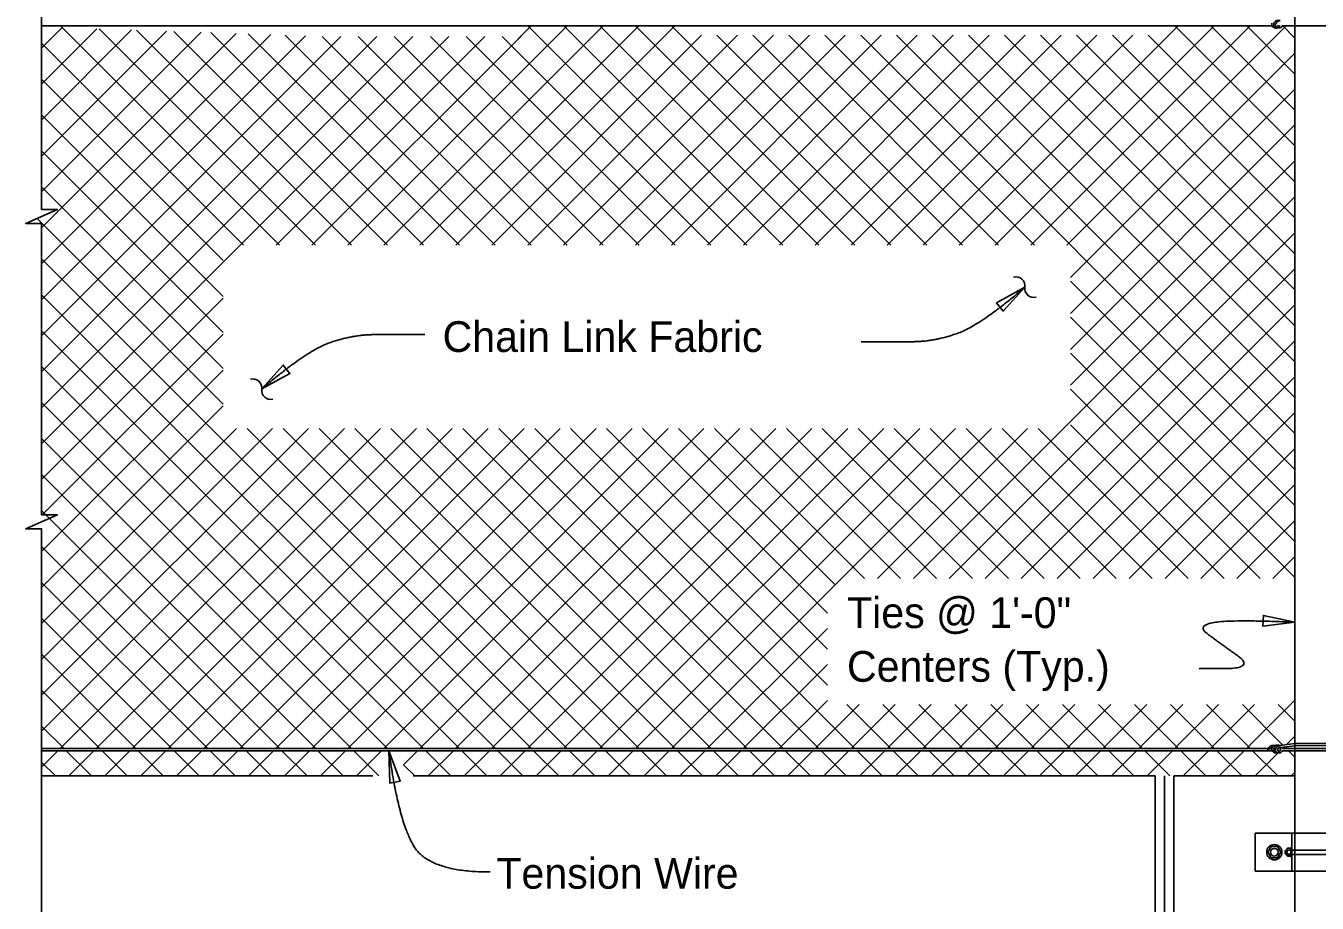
# Model space of a CAD drawing. Extents: x 0 to 41, y -96 to 25.
# Drawn here: x 16.86 to 25.32, y 14.8 to 20.56 of the extents above; entities that cross this region are included whole.
import ezdxf

# ---------------------------------------------------------------- set-up
doc = ezdxf.new("R2010")
doc.units = 0
for name, color, linetype in [('CL_Major', 7, 'Continuous'), ('Dimension', 7, 'Continuous'), ('Miscellaneous', 7, 'Continuous'), ('SteelMisc', 7, 'Continuous'), ('SteelMisc_h', 7, 'Continuous'), ('SupstrConc', 7, 'Continuous'), ('TextStructures', 7, 'Continuous')]:
    doc.layers.add(name, color=color, linetype=linetype)

msp = doc.modelspace()

# ---------------------------------------------------------------- linework, layer by layer
at = {"layer": 'CL_Major'}
msp.add_line((24.3238, 9.7541), (24.3238, 15.6384), dxfattribs=at)
at = {"layer": 'Dimension'}
for points in [[(16.9607, 22.5181), (16.9607, 19.3509), (17.064, 19.3509), (16.9607, 19.3059), (16.8574, 19.2609), (16.9607, 19.2609), (16.9607, 18.3673)], [(16.9607, 18.3673), (16.9607, 17.3495), (17.064, 17.3495), (16.9607, 17.3045), (16.8574, 17.2595), (16.9607, 17.2595), (16.9607, 15.0552)], [(16.9607, 15.3052), (16.9607, 13.4544), (17.064, 13.4544), (16.9607, 13.4094), (16.8574, 13.3644), (16.9607, 13.3644), (16.9607, 11.3636)]]:
    msp.add_lwpolyline(points, dxfattribs=at)
for points in [[(23.4077, 18.8419), (23.2222, 18.7409), (23.2658, 18.6855)], [(18.4037, 18.1753), (18.5892, 18.2762), (18.5456, 18.3317)], [(25.1779, 16.6468), (24.9713, 16.6906), (24.9684, 16.6201)], [(19.2384, 15.8029), (19.2433, 15.5918), (19.3126, 15.6052)]]:
    msp.add_lwpolyline(points, close=True, dxfattribs=at)
for centre, start, end in [((23.3481, 18.8503), 352.34263, 104.06985), ((23.4663, 18.8345), 172.34263, 284.06985), ((18.3451, 18.1827), 352.34263, 104.06985), ((18.4633, 18.1668), 172.34263, 284.06985)]:
    msp.add_arc(centre, 0.0596, start, end, dxfattribs=at)
for points in [[(22.3345, 18.4855), (22.5366, 18.4855), (22.8102, 18.4855), (23.117, 18.5934), (23.4071, 18.8423)], [(19.4725, 18.5316), (19.2748, 18.5316), (19.0012, 18.5316), (18.6944, 18.4238), (18.4043, 18.1748)], [(24.5674, 16.3422), (24.502, 16.3422), (24.922, 16.3422), (24.6718, 16.5193), (24.5346, 16.622), (24.7452, 16.6645), (25.1779, 16.6467)], [(19.9014, 15.009), (19.5036, 15.009), (19.2996, 15.3459), (19.2384, 15.8029)]]:
    msp.add_open_spline(points, degree=2, dxfattribs=at)
at = {"layer": 'Miscellaneous'}
for p, q in [((16.9607, 20.4098), (17.0951, 20.5442)), ((16.9607, 20.1741), (17.3232, 20.5366)), ((16.9607, 19.9384), (17.5512, 20.5289)), ((16.9607, 19.7027), (17.7793, 20.5213)), ((16.9607, 19.467), (18.0073, 20.5136)), ((16.9607, 19.2313), (18.2354, 20.506)), ((16.9607, 18.9956), (18.4634, 20.4983)), ((16.9607, 18.7599), (18.6915, 20.4907)), ((17.0843, 20.5552), (18.5211, 19.1184)), ((17.3392, 20.536), (18.7568, 19.1184)), ((17.5826, 20.5279), (18.992, 19.1184)), ((17.8269, 20.5197), (19.2282, 19.1184)), ((18.0708, 20.5115), (19.4639, 19.1184)), ((18.3147, 20.5033), (19.6996, 19.1184)), ((18.5566, 20.4952), (19.9334, 19.1184)), ((18.5586, 20.4951), (19.9353, 19.1184)), ((18.9691, 19.1184), (20.4059, 20.5552)), ((19.2049, 19.1184), (20.6416, 20.5552)), ((19.4406, 19.1184), (20.8773, 20.5552)), ((19.6763, 19.1184), (21.113, 20.5552)), ((19.912, 19.1184), (21.2874, 20.4939)), ((20.0834, 20.4684), (20.1702, 20.5552)), ((20.1477, 19.1184), (21.5231, 20.4939)), ((20.1484, 20.5552), (21.5852, 19.1184)), ((20.3834, 19.1184), (21.7588, 20.4939)), ((20.3841, 20.5552), (21.8209, 19.1184)), ((20.6191, 19.1184), (21.9945, 20.4939)), ((20.6198, 20.5552), (22.0566, 19.1184)), ((20.8548, 19.1184), (22.2302, 20.4939)), ((20.8555, 20.5552), (22.2923, 19.1184)), ((21.0905, 19.1184), (22.4659, 20.4939)), ((21.0912, 20.5552), (21.22, 20.4265)), ((21.3262, 19.1184), (22.7017, 20.4939)), ((21.3882, 20.4939), (22.7637, 19.1184)), ((21.5619, 19.1184), (22.9374, 20.4939)), ((21.6239, 20.4939), (22.9994, 19.1184)), ((21.7976, 19.1184), (23.1731, 20.4939)), ((21.8596, 20.4939), (23.2351, 19.1184)), ((22.0333, 19.1184), (23.4088, 20.4939)), ((22.0953, 20.4939), (23.4708, 19.1184)), ((22.269, 19.1184), (23.6445, 20.4939)), ((22.331, 20.4939), (25.1779, 17.6471)), ((22.5047, 19.1184), (23.8802, 20.4939)), ((22.5667, 20.4939), (25.1779, 17.8828)), ((22.7404, 19.1184), (24.1159, 20.4939)), ((22.8024, 20.4939), (25.1779, 18.1185)), ((22.9761, 19.1184), (24.4129, 20.5552)), ((23.0382, 20.4939), (25.1779, 18.3542)), ((23.2118, 19.1184), (24.6486, 20.5552)), ((23.2739, 20.4939), (25.1779, 18.5899)), ((23.4475, 19.1184), (24.8843, 20.5552)), ((23.5096, 20.4939), (25.1779, 18.8256)), ((23.6832, 19.1184), (25.12, 20.5552)), ((23.7453, 20.4939), (25.1779, 19.0613)), ((23.981, 20.4939), (25.1779, 19.297)), ((24.2167, 20.4939), (25.1779, 19.5327)), ((24.3911, 20.5552), (25.1779, 19.7684)), ((24.6268, 20.5552), (25.1779, 20.0041)), ((24.8625, 20.5552), (25.1779, 20.2398)), ((25.0982, 20.5552), (25.1779, 20.4755)), ((16.9607, 18.2885), (19.1592, 20.487)), ((16.9607, 18.0528), (19.3949, 20.487)), ((16.9607, 18.5242), (18.9235, 20.487)), ((16.9607, 17.8166), (19.6311, 20.487)), ((16.9607, 20.4431), (18.2854, 19.1184)), ((18.4977, 19.1184), (19.8663, 20.487)), ((18.7334, 19.1184), (20.102, 20.487)), ((18.801, 20.487), (20.1696, 19.1184)), ((19.0372, 20.487), (20.4057, 19.1184)), ((19.2733, 20.487), (20.6419, 19.1184)), ((19.5095, 20.487), (20.8781, 19.1184)), ((19.7452, 20.487), (21.1138, 19.1184)), ((19.9809, 20.487), (21.3495, 19.1184)), ((21.22, 20.4265), (22.528, 19.1184)), ((23.7072, 18.9067), (25.1779, 20.3775)), ((16.9607, 20.2074), (18.1504, 19.0177)), ((23.7072, 18.671), (25.1779, 20.1418)), ((16.9607, 19.9717), (18.1504, 18.782)), ((23.7072, 18.4353), (25.1779, 19.9061)), ((16.9607, 19.736), (18.1504, 18.5463)), ((23.7072, 18.1996), (25.1779, 19.6704)), ((16.9607, 19.5003), (18.1504, 18.3106)), ((22.6764, 16.9332), (25.1779, 19.4347)), ((16.9319, 19.2934), (18.1504, 18.0749)), ((22.9121, 16.9332), (25.1779, 19.199)), ((16.9607, 19.0289), (20.1719, 15.8177)), ((23.1478, 16.9332), (25.1779, 18.9632)), ((23.7072, 18.8821), (25.1779, 17.4113)), ((16.9607, 18.7932), (19.9362, 15.8177)), ((16.9607, 17.5814), (18.1504, 18.7711)), ((23.3835, 16.9332), (25.1779, 18.7275)), ((23.7072, 18.6464), (25.1779, 17.1756)), ((16.9607, 18.5575), (19.7005, 15.8177)), ((16.9645, 17.3495), (18.1504, 18.5354)), ((23.6192, 16.9332), (25.1779, 18.4918)), ((23.7072, 18.4107), (25.1779, 16.9399)), ((16.9607, 18.3218), (19.4648, 15.8177)), ((16.9607, 17.11), (18.1504, 18.2997)), ((23.8549, 16.9332), (25.1779, 18.2561)), ((23.7072, 18.175), (24.949, 16.9332)), ((16.9607, 18.0861), (19.2291, 15.8177)), ((16.9607, 16.8743), (18.1504, 18.064)), ((24.0906, 16.9332), (25.1779, 18.0204)), ((16.9607, 15.9315), (18.9465, 17.9172)), ((16.9607, 16.4029), (18.4751, 17.9172)), ((16.9607, 16.6386), (18.2394, 17.9172)), ((16.9607, 16.1672), (18.7108, 17.9172)), ((17.0826, 15.8177), (19.1822, 17.9172)), ((17.3183, 15.8177), (19.4179, 17.9172)), ((17.554, 15.8177), (19.6536, 17.9172)), ((17.7897, 15.8177), (19.8893, 17.9172)), ((18.0254, 15.8177), (20.125, 17.9172)), ((18.2611, 15.8177), (20.3607, 17.9172)), ((18.3081, 17.9172), (20.4076, 15.8177)), ((18.4968, 15.8177), (20.5964, 17.9172)), ((18.5438, 17.9172), (20.6433, 15.8177)), ((18.7325, 15.8177), (20.8321, 17.9172)), ((18.7795, 17.9172), (20.879, 15.8177)), ((18.9682, 15.8177), (21.0678, 17.9172)), ((19.0152, 17.9172), (21.1147, 15.8177)), ((19.2039, 15.8177), (21.3035, 17.9172)), ((19.2509, 17.9172), (21.3505, 15.8177)), ((19.4396, 15.8177), (21.5392, 17.9172)), ((19.4866, 17.9172), (21.5862, 15.8177)), ((19.6753, 15.8177), (21.7749, 17.9172)), ((19.7223, 17.9172), (21.8219, 15.8177)), ((19.911, 15.8177), (22.0106, 17.9172)), ((19.958, 17.9172), (22.0576, 15.8177)), ((20.1467, 15.8177), (22.2463, 17.9172)), ((20.1937, 17.9172), (22.2933, 15.8177)), ((20.3824, 15.8177), (22.482, 17.9172)), ((20.4294, 17.9172), (22.1126, 16.234)), ((20.6181, 15.8177), (22.7177, 17.9172)), ((20.6651, 17.9172), (22.1126, 16.4697)), ((20.8538, 15.8177), (22.9534, 17.9172)), ((20.9008, 17.9172), (22.1126, 16.7054)), ((21.0895, 15.8177), (23.1891, 17.9172)), ((21.1365, 17.9172), (22.1628, 16.8909)), ((21.3722, 17.9172), (22.3563, 16.9332)), ((21.6079, 17.9172), (22.592, 16.9332)), ((21.8436, 17.9172), (22.8277, 16.9332)), ((22.0793, 17.9172), (23.0634, 16.9332)), ((22.315, 17.9172), (23.2991, 16.9332)), ((22.4407, 16.9332), (23.4248, 17.9172)), ((22.5507, 17.9172), (23.5348, 16.9332)), ((22.7864, 17.9172), (23.7705, 16.9332)), ((23.0221, 17.9172), (24.0062, 16.9332)), ((23.2578, 17.9172), (24.2419, 16.9332)), ((23.4935, 17.9172), (24.4776, 16.9332)), ((23.7072, 17.9393), (24.7133, 16.9332)), ((16.9607, 17.8504), (18.9934, 15.8177)), ((24.3263, 16.9332), (25.1779, 17.7847)), ((16.9607, 17.6147), (18.7577, 15.8177)), ((24.562, 16.9332), (25.1779, 17.549)), ((16.9607, 17.379), (18.522, 15.8177)), ((24.7977, 16.9332), (25.1779, 17.3133)), ((16.9607, 17.1433), (18.2863, 15.8177)), ((25.0334, 16.9332), (25.1779, 17.0776)), ((16.9607, 16.9076), (18.0506, 15.8177)), ((16.9607, 16.6719), (17.8149, 15.8177)), ((21.3252, 15.8177), (22.1126, 16.6051)), ((16.9607, 16.4362), (17.5792, 15.8177)), ((21.5609, 15.8177), (22.1126, 16.3694)), ((16.9607, 16.2005), (17.3435, 15.8177)), ((21.7966, 15.8177), (22.1126, 16.1337)), ((22.0323, 15.8177), (22.3208, 16.1062)), ((22.2404, 16.1062), (22.529, 15.8177)), ((22.268, 15.8177), (22.5565, 16.1062)), ((22.4761, 16.1062), (22.7647, 15.8177)), ((22.5037, 15.8177), (22.7922, 16.1062)), ((22.7119, 16.1062), (23.0004, 15.8177)), ((22.7394, 15.8177), (23.028, 16.1062)), ((22.9476, 16.1062), (23.2361, 15.8177)), ((22.9751, 15.8177), (23.2637, 16.1062)), ((23.1833, 16.1062), (23.4718, 15.8177)), ((23.2108, 15.8177), (23.4994, 16.1062)), ((23.419, 16.1062), (23.7075, 15.8177)), ((23.4465, 15.8177), (23.7351, 16.1062)), ((23.6547, 16.1062), (23.9432, 15.8177)), ((23.6822, 15.8177), (23.9708, 16.1062)), ((23.8904, 16.1062), (24.1789, 15.8177)), ((23.9179, 15.8177), (24.2065, 16.1062)), ((24.1261, 16.1062), (24.4146, 15.8177)), ((24.1536, 15.8177), (24.4422, 16.1062)), ((24.3618, 16.1062), (24.6503, 15.8177)), ((24.3893, 15.8177), (24.6779, 16.1062)), ((24.5975, 16.1062), (24.886, 15.8177)), ((24.6251, 15.8177), (24.9136, 16.1062)), ((24.8332, 16.1062), (25.0984, 15.841)), ((24.8608, 15.8177), (25.1779, 16.1348)), ((25.0689, 16.1062), (25.1779, 15.9971)), ((16.9607, 15.9648), (17.1078, 15.8177)), ((25.1226, 15.8438), (25.1779, 15.8991)), ((16.9607, 15.6958), (17.0678, 15.8029)), ((17.1226, 15.8029), (17.287, 15.6384)), ((17.1391, 15.6384), (17.3035, 15.8029)), ((17.3583, 15.8029), (17.5227, 15.6384)), ((17.3748, 15.6384), (17.5392, 15.8029)), ((17.594, 15.8029), (17.7584, 15.6384)), ((17.6105, 15.6384), (17.7749, 15.8029)), ((17.8297, 15.8029), (17.9941, 15.6384)), ((17.8462, 15.6384), (18.0106, 15.8029)), ((18.0654, 15.8029), (18.2298, 15.6384)), ((18.0819, 15.6384), (18.2463, 15.8029)), ((18.3011, 15.8029), (18.4656, 15.6384)), ((18.3176, 15.6384), (18.482, 15.8029)), ((18.5368, 15.8029), (18.7013, 15.6384)), ((18.5533, 15.6384), (18.7177, 15.8029)), ((18.7725, 15.8029), (18.937, 15.6384)), ((18.789, 15.6384), (18.9534, 15.8029)), ((19.0082, 15.8029), (19.1727, 15.6384)), ((19.0247, 15.6384), (19.1892, 15.8029)), ((19.3344, 15.7124), (19.4249, 15.8029)), ((19.4796, 15.8029), (19.6441, 15.6384)), ((19.4961, 15.6384), (19.6606, 15.8029)), ((19.7153, 15.8029), (19.8798, 15.6384)), ((19.7318, 15.6384), (19.8963, 15.8029)), ((19.951, 15.8029), (20.1155, 15.6384)), ((19.9675, 15.6384), (20.132, 15.8029)), ((20.1867, 15.8029), (20.3512, 15.6384)), ((20.2032, 15.6384), (20.3677, 15.8029)), ((20.4224, 15.8029), (20.5869, 15.6384)), ((20.4389, 15.6384), (20.6034, 15.8029)), ((20.6581, 15.8029), (20.8226, 15.6384)), ((20.6746, 15.6384), (20.8391, 15.8029)), ((20.8938, 15.8029), (21.0583, 15.6384)), ((20.9103, 15.6384), (21.0748, 15.8029)), ((21.1295, 15.8029), (21.294, 15.6384)), ((21.146, 15.6384), (21.3105, 15.8029)), ((21.3652, 15.8029), (21.5297, 15.6384)), ((21.3817, 15.6384), (21.5462, 15.8029)), ((21.6009, 15.8029), (21.7654, 15.6384)), ((21.6174, 15.6384), (21.7819, 15.8029)), ((21.8366, 15.8029), (22.0011, 15.6384)), ((21.8531, 15.6384), (22.0176, 15.8029)), ((22.0723, 15.8029), (22.2368, 15.6384)), ((22.0888, 15.6384), (22.2533, 15.8029)), ((22.308, 15.8029), (22.4725, 15.6384)), ((22.3245, 15.6384), (22.489, 15.8029)), ((22.5437, 15.8029), (22.7082, 15.6384)), ((22.5602, 15.6384), (22.7247, 15.8029)), ((22.7794, 15.8029), (22.9439, 15.6384)), ((22.7959, 15.6384), (22.9604, 15.8029)), ((23.0151, 15.8029), (23.1796, 15.6384)), ((23.0316, 15.6384), (23.1961, 15.8029)), ((23.2508, 15.8029), (23.4153, 15.6384)), ((23.2673, 15.6384), (23.4318, 15.8029)), ((23.4865, 15.8029), (23.651, 15.6384)), ((23.503, 15.6384), (23.6675, 15.8029)), ((23.7222, 15.8029), (23.8867, 15.6384)), ((23.7387, 15.6384), (23.9032, 15.8029)), ((23.9579, 15.8029), (24.1224, 15.6384)), ((23.9744, 15.6384), (24.1389, 15.8029)), ((24.1936, 15.8029), (24.3581, 15.6384)), ((24.2101, 15.6384), (24.3746, 15.8029)), ((24.4293, 15.8029), (24.5938, 15.6384)), ((24.4458, 15.6384), (24.6103, 15.8029)), ((24.665, 15.8029), (24.8295, 15.6384)), ((24.6815, 15.6384), (24.846, 15.8029)), ((24.9007, 15.8029), (25.0652, 15.6384)), ((24.9172, 15.6384), (25.0682, 15.7894)), ((25.0011, 15.8177), (25.0046, 15.8212)), ((25.0965, 15.8177), (25.1073, 15.8285)), ((25.1105, 15.8288), (25.1217, 15.8177)), ((25.1364, 15.8029), (25.1779, 15.7614)), ((16.9607, 15.7291), (17.0513, 15.6384)), ((19.3344, 15.7124), (19.4084, 15.6384)), ((25.1529, 15.6384), (25.1779, 15.6634)), ((25.1162, 15.1316), (25.1162, 15.1437)), ((25.1219, 15.1316), (25.1219, 15.1437))]:
    msp.add_line(p, q, dxfattribs=at)
at = {"layer": 'SteelMisc'}
for p, q in [((25.1779, 14.97), (25.1779, 22.5181)), ((16.9607, 20.5552), (25.0294, 20.5552)), ((25.0943, 20.5552), (25.1779, 20.5552)), ((25.1779, 15.8503), (25.0792, 15.8387)), ((25.1779, 15.8358), (25.0853, 15.8262)), ((25.1779, 15.8503), (25.4691, 15.852)), ((25.1779, 15.8358), (25.4691, 15.8374)), ((16.9607, 15.8177), (25.0028, 15.8177)), ((16.9607, 15.8029), (25.0294, 15.8029)), ((25.0127, 15.8177), (25.0258, 15.8177)), ((25.0943, 15.8029), (25.1779, 15.8029)), ((25.0957, 15.8177), (25.1779, 15.8177)), ((24.9178, 15.2635), (25.7297, 15.2635)), ((24.9178, 15.0135), (24.9178, 15.2635)), ((25.1571, 15.2635), (25.1571, 15.0135)), ((25.1255, 15.1564), (25.1255, 15.1207)), ((25.1304, 15.1646), (25.1505, 15.1646)), ((25.1505, 15.1688), (25.1505, 15.1082)), ((25.1505, 15.1688), (25.1571, 15.1688)), ((25.1505, 15.1646), (25.1505, 15.1126)), ((25.1134, 15.1465), (25.119, 15.1531)), ((25.1134, 15.1288), (25.1134, 15.1465)), ((25.1134, 15.1288), (25.119, 15.1232)), ((25.119, 15.1531), (25.1255, 15.1531)), ((25.119, 15.1232), (25.119, 15.1531)), ((25.119, 15.1232), (25.1255, 15.1232)), ((25.1302, 15.1515), (25.1505, 15.1515)), ((25.1302, 15.1256), (25.1505, 15.1256)), ((25.1305, 15.1126), (25.1505, 15.1126)), ((25.1505, 15.1082), (25.1571, 15.1082)), ((25.7297, 15.0135), (24.9178, 15.0135)), ((25.1779, 15.0135), (25.1779, 13.7635))]:
    msp.add_line(p, q, dxfattribs=at)
msp.add_lwpolyline([(25.0211, 15.1761), (25.0644, 15.1761), (25.0861, 15.1385), (25.0644, 15.101), (25.0211, 15.101), (24.9994, 15.1385)], close=True, dxfattribs=at)
for radius in [0.05, 0.025]:
    msp.add_circle((25.0428, 15.1385), radius, dxfattribs=at)
for centre, radius, start, end in [((25.1321, 15.158), 0.00674, 104.48908, 254.18889), ((25.145, 15.1385), 0.0196, 138.62797, 221.37203), ((25.1321, 15.1191), 0.00673, 105.7823, 255.54039)]:
    msp.add_arc(centre, radius, start, end, dxfattribs=at)
for centre, major_axis, ratio, start_param, end_param in [((25.0507, 20.5677), (-0.0249, 0), 0.957868, 6.009018, 7.089857), ((25.0683, 20.5648), (0.0295, 0), 0.957868, 1.132635, 3.996184), ((25.0817, 20.5666), (-0.0303, -0.0108), 0.724765, 4.490702, 7.536078), ((25.052, 20.5637), (0.0231, 0), 0.957868, 3.779554, 4.839145), ((25.0581, 20.558), (0.0206, -0.0021), 0.798607, 4.32653, 5.275523), ((25.0728, 20.5601), (-0.00795, 0), 0.957868, 0.039428, 2.999692), ((25.0642, 20.5767), (0.0391, 0), 0.957868, 5.119309, 5.41974), ((25.0713, 20.5647), (0.0251, 0), 0.957868, 5.531357, 5.877802), ((25.037, 15.8034), (0.0373, 0), 0.957868, 1.427863, 3.108042), ((25.0495, 15.8179), (0.023, 0), 0.957868, 1.234085, 2.715751), ((25.0682, 15.8125), (0.0295, 0), 0.957868, 1.132635, 3.996184), ((25.0817, 15.8143), (-0.0303, -0.0108), 0.724765, 4.490702, 6.224248), ((25.0581, 15.7637), (-0.0724, 0), 0.957868, 5.126774, 5.652106), ((25.0506, 15.8154), (-0.0249, 0), 0.957868, 5.766165, 7.089857), ((25.052, 15.8114), (0.0231, 0), 0.957868, 3.779554, 4.839145), ((25.0581, 15.8057), (0.0206, -0.0021), 0.798607, 4.32653, 5.170153), ((25.0716, 15.8057), (0.0206, -0.0021), 0.798607, 3.319436, 5.220153), ((25.0784, 15.8102), (-0.0139, 0), 0.957868, 5.075258, 6.905413), ((25.0727, 15.8078), (-0.00795, 0), 0.957868, 0.039428, 3.031077), ((25.0868, 15.8014), (-0.0259, 0), 0.957868, 4.777514, 5.251802), ((25.071, 15.8136), (0.0119, 0), 0.957868, 5.725876, 7.416677), ((25.0642, 15.8244), (0.0391, 0), 0.957868, 5.134108, 5.41974), ((25.071, 15.8136), (0.0119, 0), 0.957868, 5.639684, 5.723117), ((25.0713, 15.8124), (0.0251, 0), 0.957868, 5.531357, 5.877802), ((25.0713, 15.8124), (0.0251, 0), 0.957868, 0.221743, 0.646747)]:
    msp.add_ellipse(centre, major_axis=major_axis, ratio=ratio, start_param=start_param, end_param=end_param, dxfattribs=at)
at = {"layer": 'SteelMisc_h'}
for p, q in [((25.1779, 20.5552), (25.4696, 20.5552)), ((25.1779, 15.8177), (25.4696, 15.8177)), ((25.1779, 15.8029), (25.4696, 15.8029)), ((25.1779, 15.2635), (25.1779, 15.0135)), ((25.4904, 15.1531), (25.1255, 15.1531)), ((25.1255, 15.1232), (25.4904, 15.1232))]:
    msp.add_line(p, q, dxfattribs=at)
at = {"layer": 'SupstrConc'}
for p, q in [((16.9607, 15.6384), (19.1327, 15.6384)), ((19.3966, 15.6384), (24.2625, 15.6384)), ((24.2625, 15.6384), (24.2625, 10.7838)), ((24.385, 15.6384), (24.385, 11.9718)), ((24.385, 15.6384), (25.1779, 15.6384))]:
    msp.add_line(p, q, dxfattribs=at)

# ---------------------------------------------------------------- texts
at = {"layer": 'Dimension'}
for s, p in [('Ties @ 1\'-0" ', (22.2413, 16.6081)), ('Centers (Typ.)', (22.2413, 16.2561))]:
    msp.add_text(s, height=0.2016, dxfattribs=at).set_placement(p)
at = {"layer": 'TextStructures'}
for s, p in [('Chain Link Fabric', (19.5898, 18.418)), ('Tension Wire', (19.9422, 14.8995))]:
    msp.add_text(s, height=0.2016, dxfattribs=at).set_placement(p)

doc.saveas('drawing.dxf')
